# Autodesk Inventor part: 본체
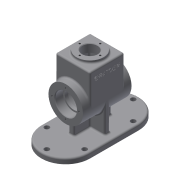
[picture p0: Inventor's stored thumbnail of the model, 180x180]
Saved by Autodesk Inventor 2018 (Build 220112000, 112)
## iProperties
Created: 2019-01
Part Number: 본체
Material: 알루미늄 6061
Document SubType Name: Modeling
Designer: mduedu
Density: 2.71 g/cm^3
Appearance: 기본값
Mass: 1057.72 g
Surface Area: 916.19 cm^2
Volume: 390.301 cm^3
Author: mduedu
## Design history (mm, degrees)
sketch "스케치1"
  geometry: C1 r 32 at (0, 0); 1 further point
  constraints: 1 centre point, 1 coincident
  dimensions: "d0" = 64 diameter of C1
extrude "돌출1" new body sketch "스케치1" stored distance "d1" = 90; taper "d2" = 0 deg
sketch "스케치2"
  geometry: L1 (0, 32)-(60, 32); L2 (60, 32)-(60, -32); L3 (60, -32)-(0, -32); L4 (0, -32)-(0, 32); C1 r 32 at (0, 0) reference; 2 further points
  constraints: 8 end point, 2 parallel, 1 coincident, 1 horizontal, 1 midpoint, 1 perpendicular, 1 tangent
  dimensions: "d5" = 60 distance between parallel lines of L4 L2
extrude "돌출2" join sketch "스케치2" stored distance "d7" = 64; taper "d8" = 0 deg
sketch "스케치3"
  geometry: C1 r 25 at (32, 32); 1 further point
  constraints: 1 centre point, 1 coincident
  dimensions: "d9" = 50 diameter of C1
extrude "돌출3" join sketch "스케치3" distance "d10" = 5; taper "d11" = 0 deg
sketch "스케치4"
  geometry: L1 (50, 25)-(0, 25); L2 (0, 25)-(0, -25); L3 (0, -25)-(50, -25); L4 (50, -25)-(50, 25); L5 (65, -25)-(65, 25) reference; A1 r 25 centre (0, 0) between (0, 25) and (0, -25); A2 r 25 centre (0, 0) between (0, -25) and (0, 25); 2 further points
  constraints: 8 end point, 4 point on circle, 2 centre point, 2 coincident, 2 parallel, 1 horizontal, 1 midpoint, 1 perpendicular, 1 tangent
  dimensions: "d12" = 50 diameter of A1; "d13" = 15 distance between parallel lines of L4 L5
extrude "돌출4" cut sketch "스케치4" stored distance "d14" = 48; taper "d15" = 0 deg
sketch "스케치5"
  geometry: C1 r 20 at (0, 0); 1 further point
  constraints: 1 centre point, 1 coincident
  dimensions: "d16" = 40 diameter of C1
extrude "돌출5" cut sketch "스케치5" distance "d17" = 15; taper "d18" = 0 deg
sketch "스케치6"
  geometry: C1 r 17 at (0, 0); 1 further point
  constraints: 1 centre point, 1 coincident
  dimensions: "d19" = 34 diameter of C1
extrude "돌출6" cut sketch "스케치6" extent not by distance; stored distance "d20" = 15; taper "d21" = 0 deg
fillet "모깎기1" dims "d22" = 0.3
fillet "모깎기2" dims "d23" = 3
fillet "모깎기3" dims "d24" = 3
fillet "모깎기4" dims "d25" = 3
fillet "모깎기5" dims "d26" = 3
fillet "모깎기6" dims "d27" = 3
sketch "스케치7"
  geometry: C1 r 14 at (0, 0); 1 further point
  constraints: 1 centre point, 1 coincident
  dimensions: "d28" = 28 diameter of C1
extrude "돌출7" cut sketch "스케치7" stored distance "d29" = 15; taper "d30" = 0 deg
chamfer "모따기1" distance "d31" = 1; stored, may be unused: second distance "d32" = 2, angle "d33" = 45 deg
chamfer "모따기2" distance "d34" = 1; stored, may be unused: second distance "d35" = 2, angle "d36" = 45 deg
node "작업 평면1"
sketch "스케치8"
  geometry: L1 (45, 45)-(-45, 45); L2 (-45, 45)-(-45, -45); L3 (-45, -45)-(45, -45); L4 (45, -45)-(45, 45); L5 (45, 45)-(-45, -45); L6 (-45, 45)-(45, -45); A1 r 45 centre (45, 0) between (45, -45) and (45, 45); A2 r 45 centre (-45, 0) between (-45, 45) and (-45, -45); A3 r 45 centre (45, 0) between (0, 0) and (45, -45); A4 r 45 centre (45, 0) between (0, 0) and (0, 0); A5 r 45 centre (45, 0) between (45, 45) and (0, 0); A6 r 45 centre (-45, 0) between (0, 0) and (-45, 45); A7 r 45 centre (-45, 0) between (-45, -45) and (0, 0); 1 further point
  constraints: 14 point on circle, 12 end point, 7 centre point, 7 midpoint, 2 parallel, 1 horizontal, 1 perpendicular
  dimensions: "d99" = 90 distance between parallel lines of L1 L3; "d101" = 90 distance between parallel lines of L2 L4
extrude "돌출8" join sketch "스케치8" distance "d41" = 10; taper "d42" = 0 deg
sketch "스케치9"
  geometry: L1 (-35, 5)-(35, 5); L2 (35, 5)-(35, -5); L3 (35, -5)-(-35, -5); L4 (-35, -5)-(-35, 5); 3 further points
  constraints: 8 end point, 2 midpoint, 2 parallel, 1 horizontal, 1 horizontal alignment, 1 perpendicular, 1 vertical alignment
  dimensions: "d52" = 10 distance of L1.end L2.end; "d54" = 70 distance of L1.start L1.end
extrude "돌출9" join sketch "스케치9" stored distance "d50" = 10; taper "d51" = 0 deg
sketch "스케치10"
  geometry: L1 (0, -25)-(47, -25) reference; L2 (50, -22)-(50, -14) reference; L3 (50, -14)-(64, -14) reference; L4 (64, -14)-(65, -15) reference; L5 (65, -15)-(65, -25) reference; L6 (65, -25)-(63, -25) reference; L7 (60, -28)-(60, -29) reference; L8 (57, -32)-(0, -32) reference; L9 (-31.607, -5)-(-55, -5) reference; L10 (-55, -5)-(-55, -45) reference; L11 (-65, -45)-(-65, 45) reference; L12 (-55, 45)-(-55, 5) reference; L13 (-55, 5)-(-31.607, 5) reference; L14 (0, 32)-(57, 32) reference; L15 (60, 29)-(60, 28) reference; L16 (63, 25)-(65, 25) reference; L17 (65, 25)-(65, 15) reference; L18 (65, 15)-(64, 14) reference; L19 (64, 14)-(50, 14) reference; L20 (50, 14)-(50, 22) reference; L21 (47, 25)-(0, 25) reference; L22 (-55, -45)-(-65, -45) reference; L23 (-65, 45)-(-55, 45) reference; L24 (0, 32)-(-55, 32); A1 r 25 centre (0, 0) between (0, 25) and (0, -25) reference; A2 r 3 centre (47, -22) between (47, -25) and (50, -22) reference; A3 r 3 centre (63, -28) between (63, -25) and (60, -28) reference; A4 r 3 centre (57, -29) between (57, -32) and (60, -29) reference; A5 r 32 centre (0, 0) between (-31.607, -5) and (0, -32) reference; A6 r 32 centre (0, 0) between (0, 32) and (-31.607, 5) reference; A7 r 3 centre (57, 29) between (60, 29) and (57, 32) reference; A8 r 3 centre (63, 28) between (60, 28) and (63, 25) reference; A9 r 3 centre (47, 22) between (50, 22) and (47, 25) reference
  constraints: 2 end point, 1 perpendicular, 1 point on line, 1 tangent
feature "리브1" sketch "스케치10" dims "d57" = 1, "d58" = 10, "d59" = 0, "d60" = 0, "d61" = 1, "d62" = 1
fillet "모깎기7" dims "d63" = 3
fillet "모깎기11" dims "d102" = 3
fillet "모깎기8" dims "d64" = 3
sketch "스케치11"
  geometry: L1 (8, -29)-(8, -8) reference; L2 (-8, -8)-(-8, -29) reference; L3 (-32, -8)-(-8, -8) reference; L4 (-38, 2)-(-38, -2) reference; L5 (-8, 8)-(-32, 8) reference; L6 (-8, 29)-(-8, 8) reference; L7 (8, 8)-(8, 29) reference; L8 (32, 8)-(8, 8) reference; L9 (38, -2)-(38, 2) reference; L10 (8, -8)-(32, -8) reference; L11 (-2, -35)-(2, -35) reference; L12 (2, 35)-(-2, 35) reference; L13 (-45, -45)-(45, -45) reference; L14 (45, 45)-(-45, 45) reference; L15 (-45, -35)-(45, -35); L16 (45, 35)-(-45, 35); A1 r 6 centre (-32, -2) between (-38, -2) and (-32, -8) reference; A2 r 6 centre (-32, 2) between (-32, 8) and (-38, 2) reference; A3 r 6 centre (32, 2) between (38, 2) and (32, 8) reference; A4 r 6 centre (32, -2) between (32, -8) and (38, -2) reference; A5 r 6 centre (2, -29) between (2, -35) and (8, -29) reference; A6 r 6 centre (-2, -29) between (-8, -29) and (-2, -35) reference; A7 r 6 centre (-2, 29) between (-2, 35) and (-8, 29) reference; A8 r 6 centre (2, 29) between (8, 29) and (2, 35) reference; A9 r 45 centre (-45, 0) between (-45, 45) and (-45, -45) reference; A10 r 45 centre (45, 0) between (45, -45) and (45, 45) reference; A11 r 35 centre (-45, 0) between (-45, 35) and (-45, -35); A12 r 35 centre (45, 0) between (45, -35) and (45, 35); 7 further points
  constraints: 6 point on circle, 4 coincident, 4 end point, 2 centre point, 3 other
  dimensions: "d103" = 10 distance between parallel lines of L16 L14
hole "구멍1" sketch "스케치11" at (-45, 35), (-80, 0), (-45, -35), (45, -35), (80, 0), (45, 35) diameter "d66" = 9; stored, may be unused: countersink angle "d70" = 90 deg, drill point angle "d72" = 118 deg; dims "d67" = 6, "d68" = 4, "d69" = 2, "d71" = 8
fillet "모깎기10" dims "d73" = 3
sketch "스케치12"
  geometry: L1 (-3, 57)-(-3, 19.596) reference; 2 further points
  constraints: 1 other
  dimensions: "d74" = 32 distance from line of point (29, 45) L1; "d75" = 45 distance of point (29, 45) point (29, 0)
feature "엠보싱1" sketch "스케치12" dims "d12" = 50, "d13" = 15, "d76" = 0.5, "d77" = 0
sketch "스케치13"
  geometry: 4 further points
  constraints: 4 other
hole "구멍2" sketch "스케치13" at (-25, 0), (0, -25), (25, 0), (0, 25) diameter "d78" = 3.242; stored, may be unused: countersink angle "d82" = 90 deg, drill point angle "d84" = 120 deg; dims "d79" = 7, "d80" = 4, "d81" = 2, "d83" = 9
sketch "스케치14"
  geometry: 4 further points
  constraints: 4 other
hole "구멍3" sketch "스케치14" at (-25, 0), (0, -25), (25, 0), (0, 25) diameter "d85" = 3.242; stored, may be unused: countersink angle "d89" = 90 deg, drill point angle "d91" = 120 deg; dims "d86" = 7, "d87" = 4, "d88" = 2, "d90" = 9
sketch "스케치15"
  geometry: 4 further points
  constraints: 4 other
hole "구멍4" sketch "스케치15" at (0, -19), (19, 0), (0, 19), (-19, 0) diameter "d92" = 3.242; stored, may be unused: countersink angle "d96" = 90 deg, drill point angle "d98" = 120 deg; dims "d93" = 8, "d94" = 4, "d95" = 2, "d97" = 10
node "솔리드1"
mirror "대칭1"
mirror "대칭2"
node "투영된 루프1"
node "투영된 루프2"
node "절단 모서리 투영1"
node "절단 모서리 투영2"
other parameters: "d37" = -65
